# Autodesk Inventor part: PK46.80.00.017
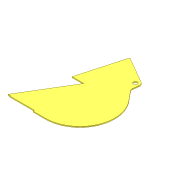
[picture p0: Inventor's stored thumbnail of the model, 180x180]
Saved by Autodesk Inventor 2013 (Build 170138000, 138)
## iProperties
Shininess: 64.0
Length Units: 11269
Angle Units: 11279
Time Units: 11290
Mass Units: 11283
Length Display Precision: 3
Angle Display Precision: 2
Compacted: True
Part Number: PK46.80.00.017
Document SubType Name: Modeling
Created: 2004-12
Material: Steel, Mild
Designer: Salex
Manufacturer: Standard
Standards Organization: Custom
Density: 7.86 g/cm^3
Mass: 57972.3 g
Surface Area: 12737.7 cm^2
Volume: 7375.62 cm^3
Density: 0.0
Volumn: 0.0
Area: 0.0
PropertySet Name: Model Information
Control State: 0
Master: False
Checked Out: False
Checked Out Date: 2008-10-15
Last Check In Date: 2008-10-15
d0: 425.000 mm
d35: 270.000 mm
d36: 420.000 mm
d10: 1155.000 mm
d11: 12.000 mm
d12: 0.00 deg
d13: 150.000 mm
d14: 450.000 mm
d15: 25.000 mm
d16: 17.000 mm
d17: 605.000 mm
d18: 50.000 mm
d19: 50.000 mm
d20: 500.000 mm
d21: 180.000 mm
d22: 205.000 mm
d23: 350.000 mm
d24: 480.000 mm
d25: 350.000 mm
d26: 1125.000 mm
d27: 365.000 mm
Author: Salex
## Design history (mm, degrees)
sketch "Sketch1"
  geometry: L1 (-384.873, 16.042)-(-239.873, 536.042); L2 (-239.873, 536.042)-(-224.873, 566.042); L3 (-224.873, 566.042)-(95.324, 379.229); L4 (-109.873, -588.958)-(-259.873, -588.958); L5 (-589.873, -563.958)-(-239.873, 16.042); L6 (-239.873, 16.042)-(-384.873, 16.042); L7 (-589.873, -563.958)-(-559.873, -563.958); L8 (-559.873, -563.958)-(-559.873, -571.958); L9 (-559.873, -571.958)-(-259.873, -571.958); L10 (-259.873, -571.958)-(-259.873, -588.958); L11 (-239.873, 16.042)-(-149.815, -38.304); L12 (218.934, 105.321)-(121.444, 224.362); L13 (110.587, 262.81)-(119.667, 329.274); C1 r 25 at (70.127, 336.042); A1 r 425 centre (-109.873, -163.958) between (-109.873, -588.958) and (218.934, 105.321); A2 r 50 centre (70.127, 336.042) between (119.667, 329.274) and (95.324, 379.229); A3 r 50 centre (160.127, 256.042) between (110.587, 262.81) and (121.444, 224.362); 1 further point
  constraints: 26 end point, 6 point on circle, 6 tangent, 4 centre point, 3 perpendicular, 2 parallel, 1 concentric, 1 equal radius, 1 horizontal, 1 point on line, 1 other
  dimensions: "d0" = 425 radius of A1; "d10" = 1155 distance from line of L2.end L4; "d13" = 150 distance from line of L10 A1.centre; "d14" = 450 distance from line of L8 A1.centre; "d15" = 25 distance from line of L5.start L4; "d16" = 17 distance between parallel lines of L9 L4; "d17" = 605 distance between parallel lines of L6 L4; "d18" = 50 radius of A2; "d19" = 50 diameter of C1; "d20" = 500 vertical distance of C1.centre A1.centre; "d21" = 180 horizontal distance of C1.centre A1.centre; "d22" = 205 horizontal distance of L1.start L5.start; "d23" = 350 horizontal distance of L5.end L5.start; "d24" = 480 horizontal distance of L5.start A1.centre; "d25" = 350 horizontal distance of L1.end L5.start; "d26" = 1125 distance from line of L1.end L4; "d27" = 365 horizontal distance of L2.end L5.start; "d28" = 124.14721 distance from line of L1.start L5 (derived); "d29" = 677.42158 distance of L5.start L5.end (derived); "d30" = 74.91642 distance from line of L1.start L11 (derived); "d35" = 270 horizontal distance of A3.centre A1.centre; "d36" = 420 vertical distance of A3.centre A1.centre
extrude "Extrusion1" new body sketch "Sketch1" distance "d11" = 12; taper "d12" = 0 deg
body "Solid1"
